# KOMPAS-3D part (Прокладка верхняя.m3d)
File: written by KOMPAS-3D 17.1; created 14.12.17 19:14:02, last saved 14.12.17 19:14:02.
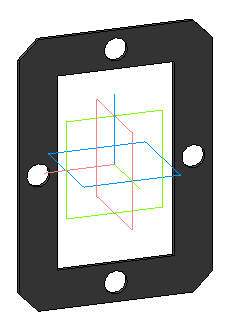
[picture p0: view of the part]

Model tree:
1. Операция без истории:1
